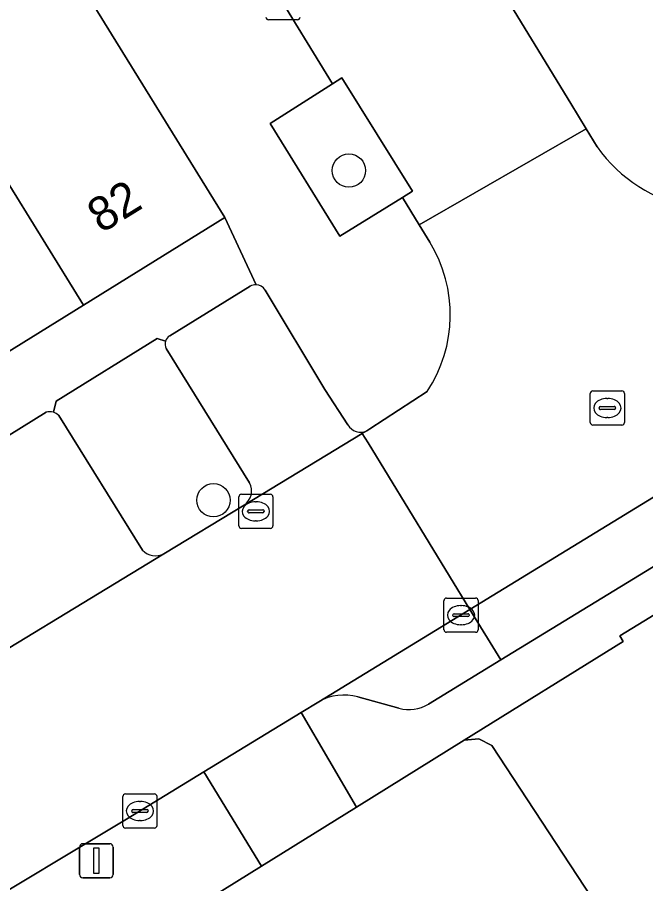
# Model space of a CAD drawing. Extents: x 159888 to 160761, y 384031 to 384750.
# Drawn here: x 160219.1 to 160237.54, y 384534.23 to 384559.64 of the extents above; entities that cross this region are included whole.
import ezdxf

# ---------------------------------------------------------------- set-up
doc = ezdxf.new("R2010")
doc.units = 0
for name, color, linetype in [('IMGEO_Boom', 7, 'Continuous'), ('IMGEO_Erf', 7, 'Continuous'), ('IMGEO_Groenvoorziening', 7, 'Continuous'), ('IMGEO_Kolk', 7, 'Continuous'), ('IMGEO_Lichtmast', 7, 'Continuous'), ('IMGEO_Pand', 7, 'Continuous'), ('IMGEO_Pand_nummerreeks', 7, 'Continuous'), ('IMGEO_Parkeervlak_open', 7, 'Continuous'), ('IMGEO_Rijbaan_lokaal_open', 7, 'Continuous'), ('IMGEO_Rioolput', 7, 'Continuous'), ('IMGEO_Voetpad_open', 7, 'Continuous')]:
    doc.layers.add(name, color=color, linetype=linetype)

msp = doc.modelspace()

# ---------------------------------------------------------------- linework, layer by layer
at = {"layer": 'IMGEO_Boom'}
for centre in [(160228.832, 384555.147), (160224.858, 384545.477)]:
    msp.add_circle(centre, 0.489, dxfattribs=at)
at = {"layer": 'IMGEO_Erf'}
msp.add_lwpolyline([(160268.727, 384561.037), (160236.781, 384541.5), (160236.88, 384541.336), (160232.217, 384538.441), (160232.643, 384538.485), (160233.023, 384538.287), (160236.574, 384532.884), (160238.073, 384530.42), (160235.324, 384528.748), (160237.931, 384524.463), (160240.21, 384525.85), (160248.414, 384512.365), (160251.931, 384506.246)], dxfattribs=at)
at = {"layer": 'IMGEO_Groenvoorziening'}
msp.add_lwpolyline([(160228.628, 384557.866), (160228.355, 384557.693), (160226.519, 384556.53), (160228.569, 384553.223), (160230.402, 384554.356), (160230.699, 384554.539)], close=True, dxfattribs=at)
for points in [[(160223.45, 384550.145), (160223.209, 384550.222), (160220.241, 384548.383), (160220.162, 384548.059)], [(160225.919, 384545.988), (160223.467, 384549.931)], [(160220.317, 384547.968), (160222.776, 384544.013)], [(160223.401, 384543.909), (160225.755, 384545.336)]]:
    msp.add_lwpolyline(points, dxfattribs=at)
for centre, radius, start, end in [((160223.714, 384550.058), 0.278, 161.7953, 207.2887), ((160220.056, 384547.701), 0.373, 45.6552, 73.5107), ((160225.466, 384545.755), 0.51, 304.6061, 27.1561), ((160223.159, 384544.382), 0.531, 223.947, 297.1581)]:
    msp.add_arc(centre, radius, start, end, dxfattribs=at)
at = {"layer": 'IMGEO_Kolk'}
for p, q in [((160227.323, 384559.568), (160226.471, 384559.568)), ((160225.602, 384544.728), (160225.602, 384545.58)), ((160225.677, 384545.654), (160226.529, 384545.654)), ((160226.603, 384545.58), (160226.603, 384544.728)), ((160226.09, 384545.434), (160226.115, 384545.434)), ((160225.861, 384545.148), (160225.861, 384545.16)), ((160226.299, 384545.111), (160225.901, 384545.111)), ((160225.904, 384545.197), (160226.302, 384545.197)), ((160226.345, 384545.16), (160226.345, 384545.148)), ((160226.113, 384544.874), (160226.088, 384544.874)), ((160226.529, 384544.654), (160225.677, 384544.654)), ((160231.622, 384541.682), (160231.622, 384542.534)), ((160231.697, 384542.608), (160232.549, 384542.608)), ((160232.623, 384542.534), (160232.623, 384541.682)), ((160232.11, 384542.388), (160232.135, 384542.388)), ((160231.881, 384542.102), (160231.881, 384542.114)), ((160232.319, 384542.065), (160231.921, 384542.065)), ((160231.924, 384542.151), (160232.322, 384542.151)), ((160232.365, 384542.114), (160232.365, 384542.102)), ((160232.133, 384541.828), (160232.108, 384541.828)), ((160232.549, 384541.608), (160231.697, 384541.608)), ((160222.275, 384536.864), (160223.127, 384536.864)), ((160222.2, 384535.938), (160222.2, 384536.79)), ((160222.688, 384536.644), (160222.713, 384536.644)), ((160223.201, 384536.79), (160223.201, 384535.938)), ((160222.459, 384536.358), (160222.459, 384536.37)), ((160222.897, 384536.321), (160222.499, 384536.321)), ((160222.502, 384536.407), (160222.9, 384536.407)), ((160222.943, 384536.37), (160222.943, 384536.358)), ((160222.711, 384536.084), (160222.686, 384536.084)), ((160223.127, 384535.864), (160222.275, 384535.864))]:
    msp.add_line(p, q, dxfattribs=at)
for points in [[(160227.323, 384559.568), (160226.471, 384559.568)], [(160225.602, 384544.728), (160225.602, 384545.58)], [(160225.677, 384545.654), (160226.529, 384545.654)], [(160226.603, 384545.58), (160226.603, 384544.728)], [(160226.529, 384544.654), (160225.677, 384544.654)], [(160231.622, 384541.682), (160231.622, 384542.534)], [(160231.697, 384542.608), (160232.549, 384542.608)], [(160232.623, 384542.534), (160232.623, 384541.682)], [(160232.549, 384541.608), (160231.697, 384541.608)], [(160222.275, 384536.864), (160223.127, 384536.864)], [(160222.2, 384535.938), (160222.2, 384536.79)], [(160223.201, 384536.79), (160223.201, 384535.938)], [(160223.127, 384535.864), (160222.275, 384535.864)]]:
    msp.add_lwpolyline(points, dxfattribs=at)
for centre, radius, start, end in [((160226.473, 384559.644), 0.0765, 181.552, 268.448), ((160226.473, 384559.644), 0.0765, 181.552, 268.448), ((160227.321, 384559.644), 0.0765, 271.552, 358.448), ((160227.321, 384559.644), 0.0765, 271.552, 358.448), ((160225.679, 384545.578), 0.0765, 91.552, 178.448), ((160225.679, 384545.578), 0.0765, 91.552, 178.448), ((160226.527, 384545.578), 0.0765, 1.552, 88.448), ((160226.527, 384545.578), 0.0765, 1.552, 88.448), ((160225.901, 384545.157), 0.0403, 85.8775, 175.7526), ((160225.898, 384545.147), 0.0366, 178.938, 274.7102), ((160226.302, 384545.154), 0.043, 264.8664, 352.4533), ((160226.306, 384545.159), 0.0386, 1.7309, 96.639), ((160225.679, 384544.73), 0.0765, 181.552, 268.448), ((160225.679, 384544.73), 0.0765, 181.552, 268.448), ((160226.527, 384544.73), 0.0765, 271.552, 358.448), ((160226.527, 384544.73), 0.0765, 271.552, 358.448), ((160231.699, 384542.532), 0.0765, 91.552, 178.448), ((160231.699, 384542.532), 0.0765, 91.552, 178.448), ((160232.547, 384542.532), 0.0765, 1.552, 88.448), ((160232.547, 384542.532), 0.0765, 1.552, 88.448), ((160231.921, 384542.111), 0.0403, 85.8775, 175.7526), ((160231.918, 384542.101), 0.0366, 178.938, 274.7102), ((160232.322, 384542.108), 0.043, 264.8664, 352.4533), ((160232.326, 384542.113), 0.0386, 1.7309, 96.639), ((160231.699, 384541.684), 0.0765, 181.552, 268.448), ((160231.699, 384541.684), 0.0765, 181.552, 268.448), ((160232.547, 384541.684), 0.0765, 271.552, 358.448), ((160232.547, 384541.684), 0.0765, 271.552, 358.448), ((160222.277, 384536.788), 0.0765, 91.552, 178.448), ((160222.277, 384536.788), 0.0765, 91.552, 178.448), ((160223.125, 384536.788), 0.0765, 1.552, 88.448), ((160223.125, 384536.788), 0.0765, 1.552, 88.448), ((160222.499, 384536.367), 0.0403, 85.8775, 175.7526), ((160222.496, 384536.357), 0.0366, 178.938, 274.7102), ((160222.9, 384536.364), 0.043, 264.8664, 352.4533), ((160222.904, 384536.369), 0.0386, 1.7309, 96.639), ((160222.277, 384535.94), 0.0765, 181.552, 268.448), ((160222.277, 384535.94), 0.0765, 181.552, 268.448), ((160223.125, 384535.94), 0.0765, 271.552, 358.448), ((160223.125, 384535.94), 0.0765, 271.552, 358.448)]:
    msp.add_arc(centre, radius, start, end, dxfattribs=at)
for centre, major_axis, ratio, start_param, end_param in [((160226.089, 384545.154), (-0.387, 0.002), 0.722429, 4.712389, 7.853982), ((160226.114, 384545.154), (-0.39, 0.002), 0.717154, 1.570796, 4.712389), ((160232.109, 384542.108), (-0.387, 0.002), 0.722429, 4.712389, 7.853982), ((160232.134, 384542.108), (-0.39, 0.002), 0.717154, 1.570796, 4.712389), ((160222.687, 384536.364), (-0.387, 0.002), 0.722429, 4.712389, 7.853982), ((160222.712, 384536.364), (-0.39, 0.002), 0.717154, 1.570796, 4.712389)]:
    msp.add_ellipse(centre, major_axis=major_axis, ratio=ratio, start_param=start_param, end_param=end_param, dxfattribs=at)
at = {"layer": 'IMGEO_Lichtmast'}
for p, q in [((160220.926, 384534.505), (160220.926, 384535.305)), ((160220.926, 384535.305), (160220.926, 384534.505)), ((160221.026, 384535.405), (160221.816, 384535.405)), ((160221.816, 384535.405), (160221.026, 384535.405)), ((160221.916, 384535.305), (160221.916, 384534.505)), ((160221.916, 384534.505), (160221.916, 384535.305)), ((160221.816, 384534.405), (160221.026, 384534.405)), ((160221.026, 384534.405), (160221.816, 384534.405))]:
    msp.add_line(p, q, dxfattribs=at)
msp.add_lwpolyline([(160221.346, 384535.28), (160221.496, 384535.28), (160221.496, 384534.53), (160221.346, 384534.53), (160221.346, 384535.28)], dxfattribs=at)
for centre, start, end in [((160221.026, 384535.305), 90, 180), ((160221.026, 384535.305), 90, 180), ((160221.816, 384535.305), 0, 90), ((160221.816, 384535.305), 360, 90), ((160221.026, 384534.505), 180, 270), ((160221.026, 384534.505), 180, 270), ((160221.816, 384534.505), 270, 0), ((160221.816, 384534.505), 270, 0)]:
    msp.add_arc(centre, 0.1, start, end, dxfattribs=at)
at = {"layer": 'IMGEO_Pand'}
for points in [[(160220.459, 384561.433), (160216.305, 384558.864), (160221.044, 384551.202), (160225.193, 384553.771)], [(160216.305, 384558.864), (160212.151, 384556.295), (160216.891, 384548.631), (160221.044, 384551.202)]]:
    msp.add_lwpolyline(points, close=True, dxfattribs=at)
at = {"layer": 'IMGEO_Parkeervlak_open'}
for points in [[(160225.934, 384551.756), (160223.574, 384550.3)], [(160228.796, 384547.692), (160228.123, 384548.73), (160226.372, 384551.641)], [(160223.467, 384549.931), (160225.919, 384545.988)], [(160219.949, 384548.064), (160214.351, 384544.588)], [(160222.776, 384544.013), (160220.317, 384547.968)], [(160225.755, 384545.336), (160229.222, 384547.434), (160229.359, 384547.517)], [(160216.476, 384539.701), (160223.401, 384543.909)], [(160231.167, 384539.5), (160233.288, 384540.795), (160232.381, 384542.278), (160227.946, 384539.569)], [(160229.09, 384539.712), (160230.301, 384539.378)], [(160219.489, 384529.735), (160222.753, 384524.374), (160223.248, 384524.697), (160223.372, 384524.341), (160233.612, 384530.57), (160233.385, 384530.944), (160236.574, 384532.884), (160233.023, 384538.287), (160232.643, 384538.485), (160232.217, 384538.441), (160229.051, 384536.475), (160226.272, 384534.749), (160219.671, 384530.65)]]:
    msp.add_lwpolyline(points, dxfattribs=at)
msp.add_lwpolyline([(160246.425, 384548.819), (160245.48, 384550.279), (160232.381, 384542.278), (160233.288, 384540.795)], close=True, dxfattribs=at)
for centre, radius, start, end in [((160226.094, 384551.491), 0.309, 87.1416, 121.0849), ((160226.095, 384551.48), 0.32, 30.1715, 87.5173), ((160223.717, 384550.058), 0.281, 120.6511, 162.0293), ((160223.714, 384550.058), 0.278, 161.7953, 207.2887), ((160220.046, 384547.678), 0.398, 73.145, 104.1656), ((160220.056, 384547.701), 0.373, 45.6552, 73.5107), ((160229.175, 384547.918), 0.442, 210.8464, 294.6195), ((160225.466, 384545.755), 0.51, 304.6061, 27.1561), ((160223.159, 384544.382), 0.531, 223.947, 297.1581), ((160228.691, 384538.256), 1.51, 74.683, 119.567), ((160230.594, 384540.435), 1.097, 254.5239, 301.5139)]:
    msp.add_arc(centre, radius, start, end, dxfattribs=at)
at = {"layer": 'IMGEO_Rijbaan_lokaal_open'}
for points in [[(160226.597, 384560.559), (160228.355, 384557.693), (160228.628, 384557.866), (160230.699, 384554.539), (160230.402, 384554.356), (160230.895, 384553.553), (160235.794, 384556.375), (160235.34, 384557.118), (160226.112, 384572.216), (160226.028, 384572.539), (160225.081, 384584.189), (160225.255, 384584.552), (160215.618, 384600.252)], [(160236.117, 384555.845), (160235.794, 384556.375), (160230.895, 384553.553), (160231.208, 384553.043)], [(160231.131, 384548.672), (160229.445, 384547.569), (160229.359, 384547.517), (160229.222, 384547.434), (160229.393, 384547.162), (160232.381, 384542.278), (160245.48, 384550.279), (160242.452, 384554.96)], [(160212.649, 384530.34), (160222.306, 384536.124), (160224.577, 384537.511), (160227.432, 384539.255), (160227.946, 384539.569), (160232.381, 384542.278), (160229.393, 384547.162), (160229.222, 384547.434), (160225.755, 384545.336), (160223.401, 384543.909), (160216.476, 384539.701), (160214.202, 384538.298), (160209.027, 384535.158), (160207.789, 384534.395), (160207.734, 384534.361), (160202.207, 384530.993)]]:
    msp.add_lwpolyline(points, dxfattribs=at)
for centre, radius, start, end in [((160239.662, 384558.347), 4.339, 215.22, 303.2078), ((160227.745, 384550.918), 4.063, 326.4468, 31.5348)]:
    msp.add_arc(centre, radius, start, end, dxfattribs=at)
at = {"layer": 'IMGEO_Rioolput'}
for p, q in [((160235.915, 384547.759), (160235.915, 384548.611)), ((160235.99, 384548.685), (160236.842, 384548.685)), ((160236.916, 384548.611), (160236.916, 384547.759)), ((160236.403, 384548.465), (160236.428, 384548.465)), ((160236.174, 384548.179), (160236.174, 384548.191)), ((160236.612, 384548.142), (160236.214, 384548.142)), ((160236.217, 384548.228), (160236.615, 384548.228)), ((160236.658, 384548.191), (160236.658, 384548.179)), ((160236.426, 384547.905), (160236.401, 384547.905)), ((160236.842, 384547.685), (160235.99, 384547.685))]:
    msp.add_line(p, q, dxfattribs=at)
for points in [[(160235.915, 384547.759), (160235.915, 384548.611)], [(160235.99, 384548.685), (160236.842, 384548.685)], [(160236.916, 384548.611), (160236.916, 384547.759)], [(160236.842, 384547.685), (160235.99, 384547.685)]]:
    msp.add_lwpolyline(points, dxfattribs=at)
for centre, radius, start, end in [((160235.992, 384548.609), 0.0765, 91.552, 178.448), ((160235.992, 384548.609), 0.0765, 91.552, 178.448), ((160236.84, 384548.609), 0.0765, 1.552, 88.448), ((160236.84, 384548.609), 0.0765, 1.552, 88.448), ((160236.214, 384548.188), 0.0403, 85.8775, 175.7526), ((160236.211, 384548.178), 0.0366, 178.938, 274.7102), ((160236.615, 384548.185), 0.043, 264.8664, 352.4533), ((160236.619, 384548.19), 0.0386, 1.7309, 96.639), ((160235.992, 384547.761), 0.0765, 181.552, 268.448), ((160235.992, 384547.761), 0.0765, 181.552, 268.448), ((160236.84, 384547.761), 0.0765, 271.552, 358.448), ((160236.84, 384547.761), 0.0765, 271.552, 358.448)]:
    msp.add_arc(centre, radius, start, end, dxfattribs=at)
for centre, major_axis, ratio, start_param, end_param in [((160236.402, 384548.185), (-0.387, 0.002), 0.722429, 4.712389, 7.853982), ((160236.427, 384548.185), (-0.39, 0.002), 0.717154, 1.570796, 4.712389)]:
    msp.add_ellipse(centre, major_axis=major_axis, ratio=ratio, start_param=start_param, end_param=end_param, dxfattribs=at)
at = {"layer": 'IMGEO_Voetpad_open'}
for points in [[(160183.852, 384603.54), (160191.506, 384608.256), (160194.085, 384604.089), (160196.664, 384599.921), (160199.243, 384595.754), (160201.822, 384591.587), (160204.401, 384587.419), (160206.98, 384583.252), (160209.559, 384579.085), (160212.138, 384574.917), (160214.717, 384570.75), (160215.907, 384568.818), (160216.709, 384567.521), (160217.169, 384566.771), (160217.276, 384566.598), (160220.459, 384561.433), (160225.193, 384553.771), (160226.109, 384551.8)], [(160229.998, 384585.344), (160233.849, 384584.805), (160234.015, 384585.993), (160228.418, 384586.778), (160225.467, 384584.995), (160225.255, 384584.552), (160225.081, 384584.189), (160226.028, 384572.539), (160226.112, 384572.216), (160235.34, 384557.118), (160235.794, 384556.375), (160236.117, 384555.845)], [(160227.946, 384539.569), (160227.432, 384539.255), (160229.051, 384536.475), (160232.217, 384538.441), (160236.88, 384541.336), (160236.781, 384541.5), (160268.727, 384561.037), (160267.235, 384563.57), (160264.233, 384561.732)], [(160231.208, 384553.043), (160230.895, 384553.553), (160230.402, 384554.356), (160228.569, 384553.223), (160226.519, 384556.53), (160228.355, 384557.693), (160226.597, 384560.559)], [(160262.757, 384558.79), (160246.425, 384548.819), (160233.288, 384540.795), (160231.167, 384539.5)], [(160226.109, 384551.8), (160225.193, 384553.771), (160221.044, 384551.202), (160216.891, 384548.631), (160212.738, 384546.06), (160208.586, 384543.489), (160204.433, 384540.918), (160200.28, 384538.347), (160196.127, 384535.776), (160192.85, 384533.747), (160191.975, 384533.205), (160187.822, 384530.635), (160183.668, 384528.065)], [(160223.574, 384550.3), (160225.934, 384551.756)], [(160226.372, 384551.641), (160228.123, 384548.73), (160228.796, 384547.692)], [(160220.162, 384548.059), (160220.241, 384548.383), (160223.209, 384550.222), (160223.45, 384550.145)], [(160229.359, 384547.517), (160229.445, 384547.569), (160231.131, 384548.672)], [(160214.351, 384544.588), (160219.949, 384548.064)], [(160230.301, 384539.378), (160229.09, 384539.712)], [(160219.671, 384530.65), (160226.272, 384534.749), (160224.577, 384537.511), (160222.306, 384536.124), (160212.649, 384530.34), (160208.363, 384527.623), (160207.672, 384527.208), (160206.965, 384526.653), (160206.625, 384526.362)]]:
    msp.add_lwpolyline(points, dxfattribs=at)
msp.add_lwpolyline([(160229.051, 384536.475), (160227.432, 384539.255), (160224.577, 384537.511), (160226.272, 384534.749)], close=True, dxfattribs=at)
for centre, radius, start, end in [((160239.662, 384558.347), 4.339, 215.22, 303.2078), ((160227.745, 384550.918), 4.063, 326.4468, 31.5348), ((160226.094, 384551.491), 0.309, 87.1416, 121.0849), ((160226.095, 384551.48), 0.32, 30.1715, 87.5173), ((160223.717, 384550.058), 0.281, 120.6511, 162.0293), ((160220.046, 384547.678), 0.398, 73.145, 104.1656), ((160229.175, 384547.918), 0.442, 210.8464, 294.6195), ((160228.691, 384538.256), 1.51, 74.683, 119.567), ((160230.594, 384540.435), 1.097, 254.5239, 301.5139)]:
    msp.add_arc(centre, radius, start, end, dxfattribs=at)

# ---------------------------------------------------------------- texts
at = {"layer": 'IMGEO_Pand_nummerreeks'}
msp.add_text('82', height=1, rotation=31.7648, dxfattribs=at).set_placement((160221.567, 384553.29))

doc.saveas('drawing.dxf')
